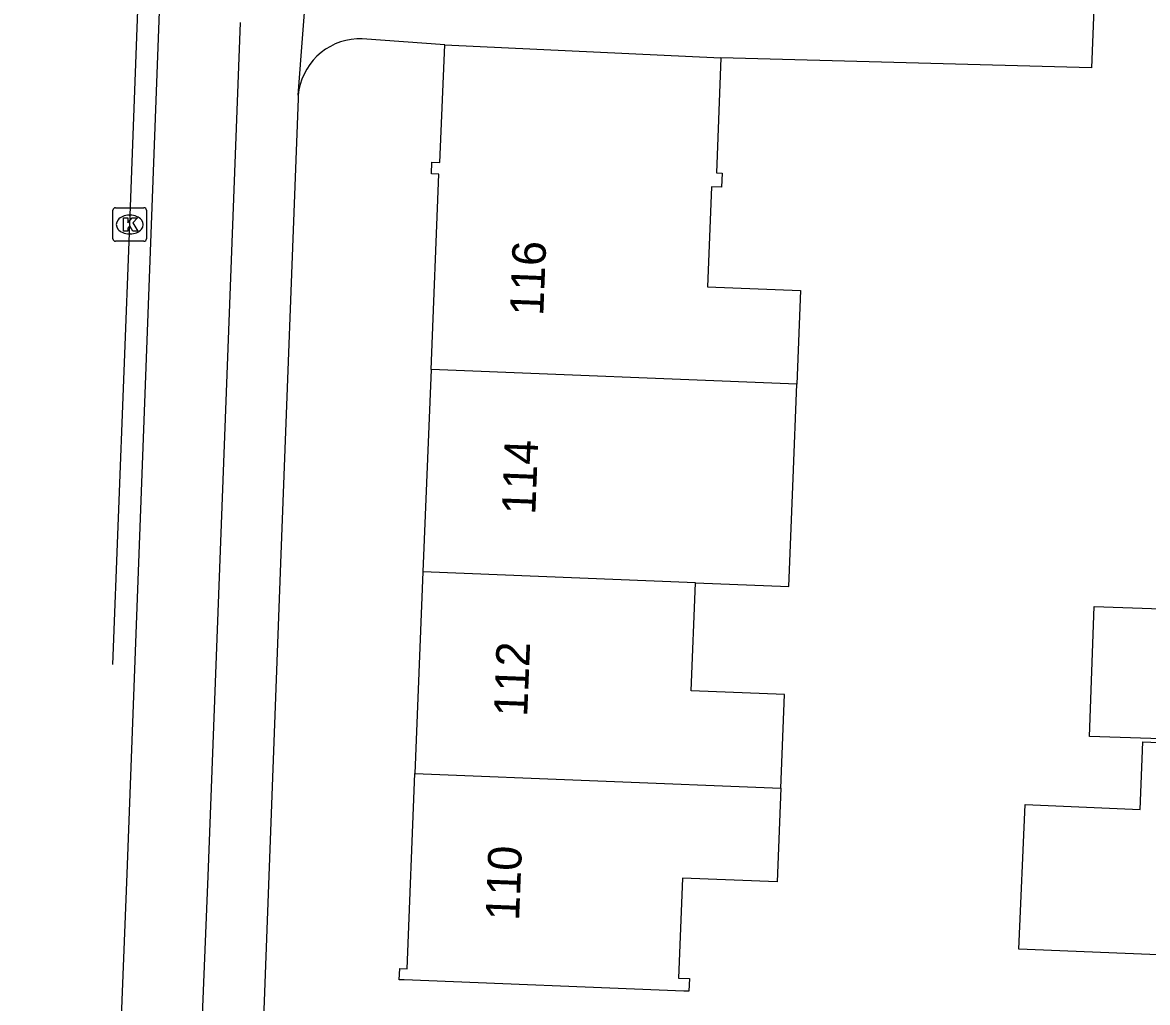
# Model space of a CAD drawing. Extents: x 161355 to 162026, y 386504 to 387459.
# Drawn here: x 161419.67 to 161453.23, y 387313.91 to 387343.15 of the extents above; entities that cross this region are included whole.
import ezdxf

# ---------------------------------------------------------------- set-up
doc = ezdxf.new("R2010")
doc.units = 0
for name, color, linetype in [('IMGEO_Fietspad_open', 7, 'Continuous'), ('IMGEO_Kolk', 7, 'Continuous'), ('IMGEO_Pand', 7, 'Continuous'), ('IMGEO_Pand_nummerreeks', 7, 'Continuous'), ('IMGEO_Rijbaan_lokaal_gesloten', 7, 'Continuous'), ('IMGEO_Voetpad_open', 7, 'Continuous')]:
    doc.layers.add(name, color=color, linetype=linetype)

msp = doc.modelspace()

# ---------------------------------------------------------------- linework, layer by layer
at = {"layer": 'IMGEO_Fietspad_open'}
for points in [[(161419.666, 387237.854), (161419.705, 387238.873), (161419.796, 387240.803), (161420.363, 387256.359), (161422.793, 387317.755), (161423.756, 387343.477)], [(161426.155, 387343.151), (161425.193, 387317.684), (161424.441, 387299.132), (161422.183, 387240.478), (161422.081, 387237.762), (161422.061, 387237.471)]]:
    msp.add_lwpolyline(points, dxfattribs=at)
at = {"layer": 'IMGEO_Kolk'}
for p, q in [((161422.438, 387337.623), (161423.29, 387337.623)), ((161422.363, 387336.697), (161422.363, 387337.549)), ((161422.851, 387337.403), (161422.876, 387337.403)), ((161423.364, 387337.549), (161423.364, 387336.697)), ((161423.29, 387336.623), (161422.438, 387336.623)), ((161422.874, 387336.843), (161422.849, 387336.843))]:
    msp.add_line(p, q, dxfattribs=at)
for points in [[(161422.438, 387337.623), (161423.29, 387337.623)], [(161422.363, 387336.697), (161422.363, 387337.549)], [(161422.684, 387337.323), (161422.807, 387337.323), (161422.807, 387337.172), (161422.937, 387337.323), (161423.101, 387337.323), (161422.955, 387337.172), (161423.108, 387336.923), (161422.956, 387336.923), (161422.871, 387337.087), (161422.807, 387337.02), (161422.807, 387336.923), (161422.684, 387336.923), (161422.684, 387337.323)], [(161423.364, 387337.549), (161423.364, 387336.697)], [(161423.29, 387336.623), (161422.438, 387336.623)]]:
    msp.add_lwpolyline(points, dxfattribs=at)
for centre, start, end in [((161422.44, 387337.547), 91.552, 178.448), ((161422.44, 387337.547), 91.552, 178.448), ((161423.288, 387337.547), 1.552, 88.448), ((161423.288, 387337.547), 1.552, 88.448), ((161422.44, 387336.699), 181.552, 268.448), ((161422.44, 387336.699), 181.552, 268.448), ((161423.288, 387336.699), 271.552, 358.448), ((161423.288, 387336.699), 271.552, 358.448)]:
    msp.add_arc(centre, 0.0765, start, end, dxfattribs=at)
for centre, major_axis, ratio, start_param, end_param in [((161422.85, 387337.123), (-0.387, 0.002), 0.722429, 4.712389, 7.853982), ((161422.875, 387337.123), (-0.39, 0.002), 0.717154, 1.570796, 4.712389)]:
    msp.add_ellipse(centre, major_axis=major_axis, ratio=ratio, start_param=start_param, end_param=end_param, dxfattribs=at)
at = {"layer": 'IMGEO_Pand'}
for points in [[(161431.856, 387332.799), (161432.089, 387338.625), (161431.869, 387338.633), (161431.882, 387338.986), (161432.12, 387338.977), (161432.264, 387342.488)], [(161432.264, 387342.488), (161440.5, 387342.093)], [(161440.5, 387342.093), (161440.371, 387338.666), (161440.539, 387338.66), (161440.523, 387338.236), (161440.217, 387338.247), (161440.104, 387335.264), (161442.881, 387335.16), (161442.77, 387332.358)], [(161431.856, 387332.799), (161431.614, 387326.766)], [(161442.77, 387332.358), (161431.856, 387332.799)], [(161439.74, 387326.438), (161442.531, 387326.325), (161442.659, 387329.556), (161442.77, 387332.358)], [(161431.614, 387326.766), (161431.373, 387320.746)], [(161439.74, 387326.438), (161431.614, 387326.766)], [(161442.292, 387320.305), (161442.403, 387323.102), (161439.612, 387323.212), (161439.74, 387326.438)], [(161455.468, 387321.718), (161451.502, 387321.855), (161451.637, 387325.727), (161455.634, 387325.588)], [(161455.731, 387315.247), (161449.389, 387315.509), (161449.575, 387319.82), (161453.006, 387319.672), (161453.093, 387321.69), (161455.463, 387321.592)], [(161442.292, 387320.305), (161442.181, 387317.512), (161439.353, 387317.624), (161439.235, 387314.642), (161439.561, 387314.629), (161439.546, 387314.25), (161439.399, 387314.256), (161431.055, 387314.588), (161430.905, 387314.594), (161430.919, 387314.928), (161431.139, 387314.919), (161431.373, 387320.746)], [(161431.373, 387320.746), (161442.292, 387320.305)]]:
    msp.add_lwpolyline(points, dxfattribs=at)
at = {"layer": 'IMGEO_Rijbaan_lokaal_gesloten'}
msp.add_lwpolyline([(161422.363, 387323.994), (161422.864, 387337.123), (161423.111, 387343.514)], dxfattribs=at)
at = {"layer": 'IMGEO_Voetpad_open'}
for points in [[(161453.163, 387382.324), (161451.556, 387341.802), (161440.5, 387342.093)], [(161427.892, 387340.981), (161428.308, 387346.454)], [(161432.264, 387342.488), (161429.804, 387342.661), (161429.639, 387342.66), (161429.474, 387342.644), (161429.312, 387342.614), (161429.153, 387342.57), (161428.999, 387342.511), (161428.85, 387342.439), (161428.709, 387342.353), (161428.576, 387342.256), (161428.452, 387342.147), (161428.338, 387342.027), (161428.235, 387341.898), (161428.144, 387341.76), (161428.066, 387341.614), (161428.002, 387341.462), (161427.951, 387341.305), (161427.914, 387341.144), (161427.892, 387340.981)], [(161427.892, 387340.981), (161427.886, 387340.885), (161427.366, 387327.023), (161426.846, 387313.16), (161426.847, 387312.983)]]:
    msp.add_lwpolyline(points, dxfattribs=at)

# ---------------------------------------------------------------- texts
at = {"layer": 'IMGEO_Pand_nummerreeks'}
for s, rotation, p in [('116', 87.7051, (161435.202, 387334.386)), ('114', 87.7026, (161434.964, 387328.457)), ('112', 87.7026, (161434.723, 387322.427)), ('110', 87.7051, (161434.479, 387316.342))]:
    msp.add_text(s, height=1, rotation=rotation, dxfattribs=at).set_placement(p)

doc.saveas('drawing.dxf')
